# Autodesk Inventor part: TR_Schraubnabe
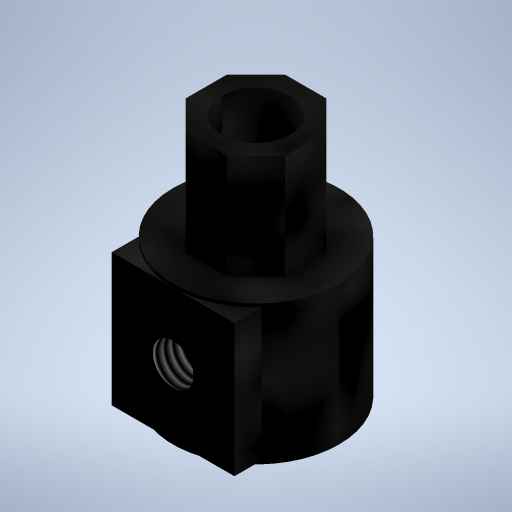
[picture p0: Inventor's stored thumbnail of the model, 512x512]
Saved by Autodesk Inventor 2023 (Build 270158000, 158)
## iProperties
Created: 2023-11
Part Number: TR_Schraubnabe
Material: PC/ABS-Kunststoff
Document SubType Name: Modeling
Designer: Administrator
Density: 0.357273 g/cm^3
Appearance: Glatt - Schwarz
Author: Administrator
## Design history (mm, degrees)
sketch "Skizze1"
  geometry: C1 r 5 at (0, 0); 1 further point
  constraints: 1 centre point, 1 coincident
  dimensions: "d0" = 10 diameter of C1 (= Einheitsmaß)
extrude "Extrusion1" new body sketch "Skizze1" distance "d1" = 8.4; taper "d2" = 0 deg
sketch "Skizze2"
  geometry: L1 (-3.7, 8.2)-(3.7, 8.2); L2 (3.7, 8.2)-(3.7, 0.2); L3 (3.7, 0.2)-(-3.7, 0.2); L4 (-3.7, 0.2)-(-3.7, 8.2); L5 (-5, 0)-(-5, 8.4) reference; 4 further points
  constraints: 8 end point, 3 midpoint, 2 parallel, 1 horizontal, 1 horizontal alignment, 1 perpendicular, 1 vertical alignment
  dimensions: "d3" = 7.4 distance of L2.end L3.end; "d4" = 8 distance of L1.end L2.end
extrude "Extrusion2" join sketch "Skizze2" distance "d5" = 5; taper "d6" = 0 deg
sketch "Skizze3"
  geometry: L1 (-3.7, 8.2)-(-3.7, 0.2) reference; 3 further points
  constraints: 1 horizontal alignment, 1 midpoint, 1 vertical alignment
hole "Bohrung1" sketch "Skizze3" at (0, 4.2) diameter "d7" = 2.459; stored, may be unused: countersink angle "d11" = 90 deg, drill point angle "d13" = 0 deg; dims "d8" = 5, "d9" = 4, "d10" = 2, "d12" = 5
sketch "Skizze4"
  geometry: L1 (-1.243, 3)-(1.243, 3); L2 (1.243, 3)-(3, 1.243); L3 (3, 1.243)-(3, -1.243); L4 (3, -1.243)-(1.243, -3); L5 (1.243, -3)-(-1.243, -3); L6 (-1.243, -3)-(-3, -1.243); L7 (-3, -1.243)-(-3, 1.243); L8 (-3, 1.243)-(-1.243, 3); 2 further points
  constraints: 16 end point, 1 coincident, 1 vertical, 17 other
  dimensions: "d14" = 6 distance between parallel lines of L1 L5 (= AchteckUmkreis)
extrude "Extrusion3" join sketch "Skizze4" distance "d15" = 6.3; taper "d16" = 0 deg
sketch "Skizze5"
  geometry: C1 r 2.05 at (0, 0); 1 further point
  constraints: 1 centre point, 1 coincident
  dimensions: "d17" = 4.1 diameter of C1 (= DAchsAufnahme)
extrude "Extrusion4" cut sketch "Skizze5" extent not by distance; stored distance "d18" = 0; taper "d19" = 0 deg
node "Volumenkörper1"
other parameters: "Einheitsmaß" = 10 [user parameter; used in 1 equation term], "Radius" = 2.075 [user parameter], "Fasen" = 0.5 [user parameter], "Dicke" = 0.8 [user parameter], "Breitloch" = 2 [user parameter], "Langloch" = 32 [user parameter], "AchteckUmkreis" = 6 [user parameter; used in 1 equation term], "DAchsAufnahme" = 4.1 [user parameter; used in 1 equation term], "AchsDurchmesser" = 4 [user parameter], "AchsFase" = 0.5 [user parameter]
